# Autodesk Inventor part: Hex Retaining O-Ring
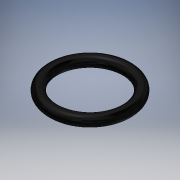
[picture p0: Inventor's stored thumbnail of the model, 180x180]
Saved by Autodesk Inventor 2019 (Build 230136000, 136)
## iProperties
Shininess: 50.0
Compacted: True
Length Units: 11272
Angle Units: 11279
Time Units: 11290
Mass Units: 11286
Length Display Precision: 4
Angle Display Precision: 2
Company: Autodesk
Created: 2000-05
Part Number: Hex Retaining O-Ring
Project: Inventor Samples
User Status: IN PROGRESS
Document SubType Name: Modeling
Designer: Autodesk, Inc.
Density: 1.13 g/cm^3
Material: Nylon-6/6
Mass: 0.0755667 g
Surface Area: 1.68499 cm^2
Volume: 0.0668732 cm^3
Appearance: Glossy - Black
Density: 0.0
Volumn: 0.0
Area: 0.0
PropertySet Name: Model Information
Control State: 0
Master: False
Checked Out: False
Checked Out Date: 2018-05-30
Last Check In Date: 2018-05-30
Author: Autodesk, Inc.
Revision Number: A
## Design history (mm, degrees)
node "Revolution1" dims "d2" = 90 deg
  sketch "Sketch2" dims "d1" = 1.5875
    geometry: L1 (-4.285, 8.08)-(-4.285, 11.134) reference; 2 further points
    constraints: 2 end point, 2 vertical, 2 vertical alignment, 2 other
    dimensions: "d0" = 10.75436 diameter of point (1.092, 9.11) L1
workaxis "Work Axis1"
workplane "Work Plane1"
body "Solid1"
